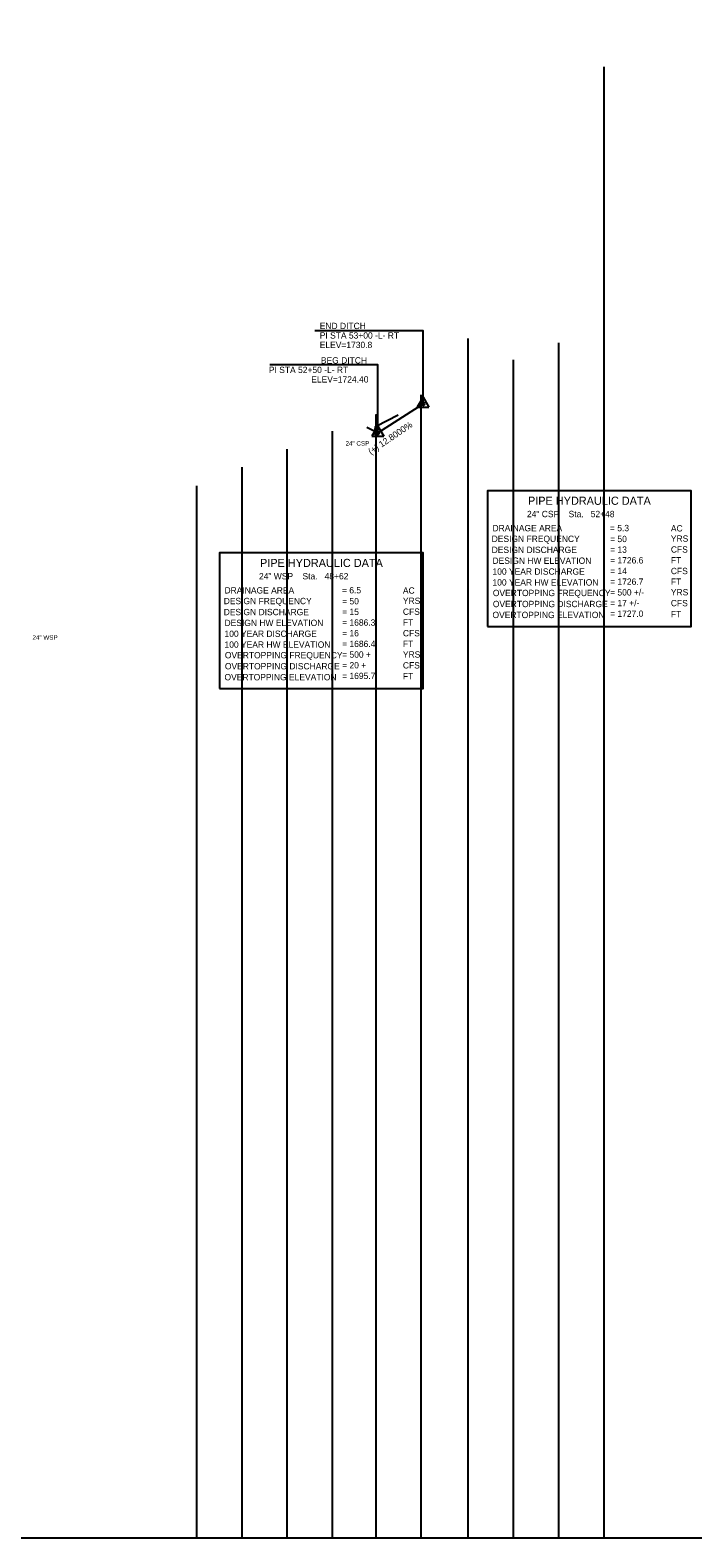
# Model space of a CAD drawing. Extents: x 1025306 to 1036906, y 638983 to 643947.
# Drawn here: x 1029171 to 1029904, y 639889 to 641557 of the extents above; entities that cross this region are included whole.
import ezdxf

# ---------------------------------------------------------------- set-up
doc = ezdxf.new("R2010")
doc.units = 0
for name, color, linetype in [('Default', 7, 'Continuous'), ('Prop PFL Cross Pipe CELL', 7, 'Continuous'), ('Prop PFL Cross Pipe Text CELL', 7, 'Continuous'), ('Prop PFL Pipe Hydraulic Data CELL', 7, 'Continuous'), ('Prop Vertical Profile Ditch Grade Right', 7, 'Continuous'), ('Prop Vertical Profile Ditch Grade Right Label', 7, 'Continuous'), ('Prop VPI Ditch Grade Right Label', 7, 'Continuous'), ('Scratch_Level_0', 7, 'Continuous'), ('Scratch_Level_1', 7, 'Continuous')]:
    doc.layers.add(name, color=color, linetype=linetype)

msp = doc.modelspace()

# ---------------------------------------------------------------- linework, layer by layer
at = {"layer": 'Default'}
for p, q in [((1029605.6, 641150.9), (1029599.1, 641139.7)), ((1029605.6, 641150.9), (1029612.1, 641139.7)), ((1029599.1, 641139.7), (1029612.1, 641139.7)), ((1029555.6, 641118.9), (1029549.1, 641107.7)), ((1029555.6, 641118.9), (1029562.1, 641107.7)), ((1029549.1, 641107.7), (1029562.1, 641107.7))]:
    msp.add_line(p, q, dxfattribs=at)
for centre, radius in [((1029605.6, 641143.4), 1.75), ((1029605.6, 641143.4), 1.2), ((1029555.6, 641111.4), 1.75), ((1029555.6, 641111.4), 1.2)]:
    msp.add_circle(centre, radius, dxfattribs=at)
at = {"layer": 'Prop PFL Cross Pipe CELL'}
msp.add_ellipse((1029553.6, 641113.7), major_axis=(0, 5), ratio=0.2, dxfattribs=at)
at = {"layer": 'Prop PFL Pipe Hydraulic Data CELL'}
for points in [[(1029676.7, 640897.4), (1029901.7, 640897.4), (1029901.7, 641047.4), (1029676.7, 641047.4)], [(1029380.6, 640828.6), (1029605.6, 640828.6), (1029605.6, 640978.6), (1029380.6, 640978.6)]]:
    msp.add_lwpolyline(points, close=True, dxfattribs=at)
at = {"layer": 'Prop Vertical Profile Ditch Grade Right'}
msp.add_line((1029555.6, 641111.4), (1029605.6, 641143.4), dxfattribs=at)
at = {"layer": 'Prop VPI Ditch Grade Right Label'}
for points in [[(1029605.6, 641143.4), (1029605.6, 641224.3), (1029486.1, 641224.3)], [(1029555.6, 641111.4), (1029555.6, 641186.5), (1029436.1, 641186.5)]]:
    msp.add_lwpolyline(points, dxfattribs=at)
for centre in [(1029605.6, 641143.4), (1029555.6, 641111.4)]:
    msp.add_circle(centre, 0.5, dxfattribs=at)
at = {"layer": 'Scratch_Level_0'}
msp.add_line((1025305.6, 639889.4), (1029505.6, 639889.4), dxfattribs=at)
for points in [[(1025305.6, 639889.4), (1033905.6, 639889.4), (1033905.6, 643046.4)], [(1025305.6, 639889.4), (1033375.6, 639889.4), (1033375.6, 642934.5)], [(1025305.6, 639889.4), (1035605.6, 639889.4), (1035605.6, 642735.7)], [(1025305.6, 639889.4), (1035600.4, 639889.4), (1035600.4, 642734.5)], [(1025305.6, 639889.4), (1035578, 639889.4), (1035578, 642729)], [(1025305.6, 639889.4), (1035555.6, 639889.4), (1035555.6, 642723.6)], [(1025305.6, 639889.4), (1035514.6, 639889.4), (1035514.6, 642713.6)], [(1025305.6, 639889.4), (1035505.6, 639889.4), (1035505.6, 642711.4)], [(1025305.6, 639889.4), (1035455.6, 639889.4), (1035455.6, 642699.2)], [(1025305.6, 639889.4), (1035405.6, 639889.4), (1035405.6, 642687.9)], [(1025305.6, 639889.4), (1033855.6, 639889.4), (1033855.6, 642684.6)], [(1025305.6, 639889.4), (1034755.6, 639889.4), (1034755.6, 642682.7)], [(1025305.6, 639889.4), (1035205.6, 639889.4), (1035205.6, 642658.7)], [(1025305.6, 639889.4), (1035155.6, 639889.4), (1035155.6, 642655.4)], [(1025305.6, 639889.4), (1035105.6, 639889.4), (1035105.6, 642653.6)], [(1025305.6, 639889.4), (1035055.6, 639889.4), (1035055.6, 642653.4)], [(1025305.6, 639889.4), (1033655.6, 639889.4), (1033655.6, 642644)], [(1025305.6, 639889.4), (1032988.4, 639889.4), (1032988.4, 642410.8)], [(1025305.6, 639889.4), (1031301.6, 639889.4), (1031301.6, 641735.1)], [(1025305.6, 639889.4), (1029805.6, 639889.4), (1029805.6, 641516)], [(1025305.6, 639889.4), (1029655.6, 639889.4), (1029655.6, 641215.6)], [(1025305.6, 639889.4), (1029755.6, 639889.4), (1029755.6, 641210.8)], [(1025305.6, 639889.4), (1029705.6, 639889.4), (1029705.6, 641192.2)], [(1029553.6, 639889.4), (1029603.6, 639889.4), (1029603.6, 641153.3)], [(1025305.6, 639889.4), (1029553.6, 639889.4), (1029553.6, 641131.2)], [(1029553.6, 641132.2), (1029553.6, 641118.7), (1029578.2, 641131.2)], [(1025305.6, 639889.4), (1029505.6, 639889.4), (1029505.6, 641113.1)], [(1025305.6, 639889.4), (1029455.6, 639889.4), (1029455.6, 641093.2)], [(1025305.6, 639889.4), (1029405.6, 639889.4), (1029405.6, 641073.3)], [(1029355.6, 639889.4), (1029355.6, 641052.9)]]:
    msp.add_lwpolyline(points, dxfattribs=at)
at = {"layer": 'Scratch_Level_1'}
msp.add_line((1025305.6, 639889.4), (1032987.6, 639889.4), dxfattribs=at)
for points in [[(1025305.6, 639889.4), (1032987.6, 639889.4), (1032987.6, 642398)], [(1025305.6, 639889.4), (1032571.6, 639889.4), (1032571.6, 642222.1)], [(1025305.6, 639889.4), (1031338.6, 639889.4), (1031338.6, 641754.5)], [(1025305.6, 639889.4), (1031300.6, 639889.4), (1031300.6, 641742.5)], [(1029553.6, 641132.2), (1029553.6, 641112.2), (1029543.6, 641117.1)]]:
    msp.add_lwpolyline(points, dxfattribs=at)

# ---------------------------------------------------------------- texts
at = {"layer": 'Prop PFL Cross Pipe Text CELL'}
for s, p in [('24" CSP', (1029519.9, 641097.2)), ('24" WSP', (1029174, 640882.5))]:
    msp.add_text(s, height=5, dxfattribs=at).set_placement(p)
at = {"layer": 'Prop PFL Pipe Hydraulic Data CELL'}
for s, height, p in [('PIPE HYDRAULIC DATA', 9, (1029721.5, 641031.8)), ('  24" CSP    Sta.   52+48  ', 7, (1029715.2, 641018.1)), ('DESIGN FREQUENCY', 7, (1029681.4, 640990.7)), ('DRAINAGE AREA', 7, (1029682.3, 641002.5)), ('= 5.3 ', 7, (1029812.1, 641002.6)), ('= 50 ', 7, (1029812.3, 640990.5)), ('AC', 7, (1029879.4, 641002.3)), ('YRS', 7, (1029879.4, 640990.9)), ('DESIGN DISCHARGE', 7, (1029681.4, 640978.5)), ('= 13 ', 7, (1029812.3, 640978.7)), ('CFS', 7, (1029879.4, 640978.9)), ('PIPE HYDRAULIC DATA', 9, (1029425.4, 640963)), ('100 YEAR DISCHARGE', 7, (1029682.3, 640954.5)), ('DESIGN HW ELEVATION', 7, (1029682.3, 640966.5)), ('= 1726.6', 7, (1029812.3, 640966.9)), ('= 14 ', 7, (1029812.3, 640955.1)), ('CFS', 7, (1029879.4, 640955.1)), ('FT', 7, (1029879.4, 640966.9)), ('  24" WSP    Sta.   48+62  ', 7, (1029419.1, 640949.3)), ('100 YEAR HW ELEVATION', 7, (1029682.3, 640942.5)), ('= 1726.7', 7, (1029812.3, 640943.3)), ('FT', 7, (1029879.4, 640943.3)), ('DESIGN FREQUENCY', 7, (1029385.3, 640921.9)), ('DRAINAGE AREA', 7, (1029386.2, 640933.7)), ('= 6.5 ', 7, (1029516, 640933.8)), ('= 50 ', 7, (1029516.2, 640921.7)), ('AC', 7, (1029583.3, 640933.5)), ('YRS', 7, (1029583.3, 640922.1)), ('OVERTOPPING FREQUENCY', 7, (1029682.7, 640930.8)), ('= 500 +/-', 7, (1029812.3, 640931.5)), ('YRS', 7, (1029879.4, 640931.6)), ('DESIGN DISCHARGE', 7, (1029385.3, 640909.7)), ('= 15 ', 7, (1029516.2, 640909.9)), ('CFS', 7, (1029583.3, 640910.1)), ('OVERTOPPING ELEVATION', 7, (1029682.3, 640906.5)), ('OVERTOPPING DISCHARGE', 7, (1029682.7, 640918.6)), ('= 17 +/-', 7, (1029812.3, 640919.7)), ('= 1727.0', 7, (1029812.3, 640907.9)), ('CFS', 7, (1029879.4, 640919.6)), ('FT', 7, (1029879.4, 640907.5)), ('DESIGN HW ELEVATION', 7, (1029386.2, 640897.7)), ('= 1686.3', 7, (1029516.2, 640898.1)), ('FT', 7, (1029583.3, 640898.1)), ('100 YEAR DISCHARGE', 7, (1029386.2, 640885.7)), ('100 YEAR HW ELEVATION', 7, (1029386.2, 640873.7)), ('= 16 ', 7, (1029516.2, 640886.3)), ('= 1686.4', 7, (1029516.2, 640874.5)), ('CFS', 7, (1029583.3, 640886.3)), ('FT', 7, (1029583.3, 640874.5)), ('OVERTOPPING FREQUENCY', 7, (1029386.6, 640862)), ('= 500 + ', 7, (1029516.2, 640862.7)), ('YRS', 7, (1029583.3, 640862.8)), ('OVERTOPPING ELEVATION', 7, (1029386.2, 640837.7)), ('OVERTOPPING DISCHARGE', 7, (1029386.6, 640849.8)), ('= 20 +  ', 7, (1029516.2, 640850.9)), ('= 1695.7', 7, (1029516.2, 640839.1)), ('CFS', 7, (1029583.3, 640850.8)), ('FT', 7, (1029583.3, 640838.7))]:
    msp.add_text(s, height=height, dxfattribs=at).set_placement(p)
at = {"layer": 'Prop Vertical Profile Ditch Grade Right Label'}
msp.add_text('(+) 12.8000%', height=7, rotation=34.2157, dxfattribs=at).set_placement((1029547.9, 641086.9))
at = {"layer": 'Prop VPI Ditch Grade Right Label'}
for s, p in [('END DITCH', (1029491.4, 641226.1)), ('PI STA 53+00 -L- RT', (1029491.4, 641215.6)), ('ELEV=1730.8', (1029491.4, 641205.1)), ('BEG DITCH', (1029492.7, 641188)), ('PI STA 52+50 -L- RT', (1029435.2, 641177.5)), ('ELEV=1724.40', (1029482, 641167))]:
    msp.add_text(s, height=7, dxfattribs=at).set_placement(p)

doc.saveas('drawing.dxf')
